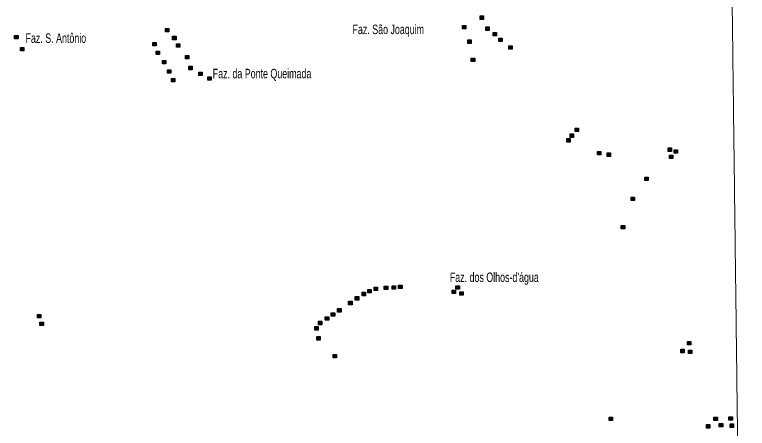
# Model space of a CAD drawing. Extents: x 265.7 to 292.1, y 7676.2 to 7704.2.
# Drawn here: x 285.92 to 292.1, y 7683.19 to 7686.68 of the extents above; entities that cross this region are included whole.
import ezdxf

# ---------------------------------------------------------------- set-up
doc = ezdxf.new("R2010")
doc.units = 0
doc.header["$LTSCALE"] = 0.032
doc.layers.add('2', color=7, linetype='Continuous', lineweight=25)
doc.layers.add('63', color=7, linetype='Continuous', lineweight=13)
doc.layers.add('61', color=7, linetype='Continuous')

msp = doc.modelspace()

# ---------------------------------------------------------------- hatches: boundary and pattern name
at = {"layer": '2'}
for points in [[(289.8456, 7686.6737), (289.8746, 7686.6737), (289.8746, 7686.6447), (289.8456, 7686.6447)], [(287.1895, 7686.5679), (287.2185, 7686.5679), (287.2185, 7686.5389), (287.1895, 7686.5389)], [(289.6962, 7686.5939), (289.7252, 7686.5939), (289.7252, 7686.5649), (289.6962, 7686.5649)], [(289.8931, 7686.5808), (289.9221, 7686.5808), (289.9221, 7686.5518), (289.8931, 7686.5518)], [(285.916, 7686.5098), (285.945, 7686.5098), (285.945, 7686.4808), (285.916, 7686.4808)], [(287.25, 7686.5019), (287.279, 7686.5019), (287.279, 7686.4729), (287.25, 7686.4729)], [(289.9561, 7686.5349), (289.9851, 7686.5349), (289.9851, 7686.5059), (289.9561, 7686.5059)], [(290.0045, 7686.4858), (290.0335, 7686.4858), (290.0335, 7686.4568), (290.0045, 7686.4568)], [(287.0822, 7686.4493), (287.1112, 7686.4493), (287.1112, 7686.4203), (287.0822, 7686.4203)], [(287.2823, 7686.4389), (287.3113, 7686.4389), (287.3113, 7686.4099), (287.2823, 7686.4099)], [(289.7422, 7686.4711), (289.7712, 7686.4711), (289.7712, 7686.4421), (289.7422, 7686.4421)], [(290.0875, 7686.4219), (290.1165, 7686.4219), (290.1165, 7686.3929), (290.0875, 7686.3929)], [(285.9644, 7686.4073), (285.9934, 7686.4073), (285.9934, 7686.3783), (285.9644, 7686.3783)], [(287.1104, 7686.3767), (287.1394, 7686.3767), (287.1394, 7686.3477), (287.1104, 7686.3477)], [(287.1638, 7686.2977), (287.1928, 7686.2977), (287.1928, 7686.2687), (287.1638, 7686.2687)], [(287.3575, 7686.3412), (287.3865, 7686.3412), (287.3865, 7686.3122), (287.3575, 7686.3122)], [(289.771, 7686.3172), (289.8, 7686.3172), (289.8, 7686.2882), (289.771, 7686.2882)], [(287.3864, 7686.2492), (287.4154, 7686.2492), (287.4154, 7686.2202), (287.3864, 7686.2202)], [(287.2056, 7686.22), (287.2346, 7686.22), (287.2346, 7686.191), (287.2056, 7686.191)], [(287.4712, 7686.2), (287.5002, 7686.2), (287.5002, 7686.171), (287.4712, 7686.171)], [(287.2396, 7686.1458), (287.2686, 7686.1458), (287.2686, 7686.1168), (287.2396, 7686.1168)], [(287.5463, 7686.1596), (287.5753, 7686.1596), (287.5753, 7686.1306), (287.5463, 7686.1306)], [(290.6065, 7685.6785), (290.6355, 7685.6785), (290.6355, 7685.6495), (290.6065, 7685.6495)], [(290.6478, 7685.7278), (290.6768, 7685.7278), (290.6768, 7685.6988), (290.6478, 7685.6988)], [(290.5776, 7685.639), (290.6066, 7685.639), (290.6066, 7685.61), (290.5776, 7685.61)], [(291.4336, 7685.5603), (291.4626, 7685.5603), (291.4626, 7685.5313), (291.4336, 7685.5313)], [(290.8365, 7685.5308), (290.8655, 7685.5308), (290.8655, 7685.5018), (290.8365, 7685.5018)], [(290.9189, 7685.518), (290.9479, 7685.518), (290.9479, 7685.489), (290.9189, 7685.489)], [(291.4451, 7685.4987), (291.4741, 7685.4987), (291.4741, 7685.4697), (291.4451, 7685.4697)], [(291.4838, 7685.5446), (291.5128, 7685.5446), (291.5128, 7685.5156), (291.4838, 7685.5156)], [(291.2361, 7685.3137), (291.2651, 7685.3137), (291.2651, 7685.2847), (291.2361, 7685.2847)], [(291.1208, 7685.146), (291.1498, 7685.146), (291.1498, 7685.117), (291.1208, 7685.117)], [(291.0376, 7684.9055), (291.0666, 7684.9055), (291.0666, 7684.8765), (291.0376, 7684.8765)], [(288.9513, 7684.3849), (288.9803, 7684.3849), (288.9803, 7684.3559), (288.9513, 7684.3559)], [(289.0369, 7684.3938), (289.0659, 7684.3938), (289.0659, 7684.3648), (289.0369, 7684.3648)], [(289.103, 7684.3961), (289.132, 7684.3961), (289.132, 7684.3671), (289.103, 7684.3671)], [(289.1579, 7684.4018), (289.1869, 7684.4018), (289.1869, 7684.3728), (289.1579, 7684.3728)], [(289.6421, 7684.397), (289.6711, 7684.397), (289.6711, 7684.368), (289.6421, 7684.368)], [(288.8495, 7684.3421), (288.8785, 7684.3421), (288.8785, 7684.3131), (288.8495, 7684.3131)], [(288.8973, 7684.3655), (288.9263, 7684.3655), (288.9263, 7684.3365), (288.8973, 7684.3365)], [(289.6092, 7684.3598), (289.6382, 7684.3598), (289.6382, 7684.3308), (289.6092, 7684.3308)], [(289.6736, 7684.3461), (289.7026, 7684.3461), (289.7026, 7684.3171), (289.6736, 7684.3171)], [(288.7359, 7684.2662), (288.7649, 7684.2662), (288.7649, 7684.2372), (288.7359, 7684.2372)], [(288.7923, 7684.3057), (288.8213, 7684.3057), (288.8213, 7684.2767), (288.7923, 7684.2767)], [(288.643, 7684.2041), (288.672, 7684.2041), (288.672, 7684.1751), (288.643, 7684.1751)], [(286.108, 7684.1557), (286.137, 7684.1557), (286.137, 7684.1267), (286.108, 7684.1267)], [(288.5389, 7684.1355), (288.5679, 7684.1355), (288.5679, 7684.1065), (288.5389, 7684.1065)], [(288.589, 7684.1695), (288.618, 7684.1695), (288.618, 7684.1405), (288.589, 7684.1405)], [(286.1298, 7684.0896), (286.1588, 7684.0896), (286.1588, 7684.0606), (286.1298, 7684.0606)], [(288.4808, 7684.0976), (288.5098, 7684.0976), (288.5098, 7684.0686), (288.4808, 7684.0686)], [(288.4501, 7684.0524), (288.4791, 7684.0524), (288.4791, 7684.0234), (288.4501, 7684.0234)], [(288.4671, 7683.9684), (288.4961, 7683.9684), (288.4961, 7683.9394), (288.4671, 7683.9394)], [(291.596, 7683.9265), (291.625, 7683.9265), (291.625, 7683.8975), (291.596, 7683.8975)], [(288.6042, 7683.8184), (288.6332, 7683.8184), (288.6332, 7683.7894), (288.6042, 7683.7894)], [(291.5402, 7683.8611), (291.5692, 7683.8611), (291.5692, 7683.8321), (291.5402, 7683.8321)], [(291.6057, 7683.8538), (291.6347, 7683.8538), (291.6347, 7683.8248), (291.6057, 7683.8248)], [(290.9358, 7683.289), (290.9648, 7683.289), (290.9648, 7683.26), (290.9358, 7683.26)], [(291.8204, 7683.2897), (291.8494, 7683.2897), (291.8494, 7683.2607), (291.8204, 7683.2607)], [(291.9473, 7683.2919), (291.9763, 7683.2919), (291.9763, 7683.2629), (291.9473, 7683.2629)], [(291.7567, 7683.2251), (291.7857, 7683.2251), (291.7857, 7683.1961), (291.7567, 7683.1961)], [(291.8649, 7683.2356), (291.8939, 7683.2356), (291.8939, 7683.2066), (291.8649, 7683.2066)], [(291.9576, 7683.2307), (291.9866, 7683.2307), (291.9866, 7683.2017), (291.9576, 7683.2017)]]:
    msp.add_hatch(color=256, dxfattribs=at).paths.add_polyline_path(points)

# ---------------------------------------------------------------- linework, layer by layer
for points in [[(289.8456, 7686.6737), (289.8746, 7686.6737), (289.8746, 7686.6447), (289.8456, 7686.6447)], [(287.1895, 7686.5679), (287.2185, 7686.5679), (287.2185, 7686.5389), (287.1895, 7686.5389)], [(289.6962, 7686.5939), (289.7252, 7686.5939), (289.7252, 7686.5649), (289.6962, 7686.5649)], [(289.8931, 7686.5808), (289.9221, 7686.5808), (289.9221, 7686.5518), (289.8931, 7686.5518)], [(285.916, 7686.5098), (285.945, 7686.5098), (285.945, 7686.4808), (285.916, 7686.4808)], [(287.25, 7686.5019), (287.279, 7686.5019), (287.279, 7686.4729), (287.25, 7686.4729)], [(289.9561, 7686.5349), (289.9851, 7686.5349), (289.9851, 7686.5059), (289.9561, 7686.5059)], [(290.0045, 7686.4858), (290.0335, 7686.4858), (290.0335, 7686.4568), (290.0045, 7686.4568)], [(287.0822, 7686.4493), (287.1112, 7686.4493), (287.1112, 7686.4203), (287.0822, 7686.4203)], [(287.2823, 7686.4389), (287.3113, 7686.4389), (287.3113, 7686.4099), (287.2823, 7686.4099)], [(289.7422, 7686.4711), (289.7712, 7686.4711), (289.7712, 7686.4421), (289.7422, 7686.4421)], [(290.0875, 7686.4219), (290.1165, 7686.4219), (290.1165, 7686.3929), (290.0875, 7686.3929)], [(285.9644, 7686.4073), (285.9934, 7686.4073), (285.9934, 7686.3783), (285.9644, 7686.3783)], [(287.1104, 7686.3767), (287.1394, 7686.3767), (287.1394, 7686.3477), (287.1104, 7686.3477)], [(287.1638, 7686.2977), (287.1928, 7686.2977), (287.1928, 7686.2687), (287.1638, 7686.2687)], [(287.3575, 7686.3412), (287.3865, 7686.3412), (287.3865, 7686.3122), (287.3575, 7686.3122)], [(289.771, 7686.3172), (289.8, 7686.3172), (289.8, 7686.2882), (289.771, 7686.2882)], [(287.3864, 7686.2492), (287.4154, 7686.2492), (287.4154, 7686.2202), (287.3864, 7686.2202)], [(287.2056, 7686.22), (287.2346, 7686.22), (287.2346, 7686.191), (287.2056, 7686.191)], [(287.4712, 7686.2), (287.5002, 7686.2), (287.5002, 7686.171), (287.4712, 7686.171)], [(287.2396, 7686.1458), (287.2686, 7686.1458), (287.2686, 7686.1168), (287.2396, 7686.1168)], [(287.5463, 7686.1596), (287.5753, 7686.1596), (287.5753, 7686.1306), (287.5463, 7686.1306)], [(290.6065, 7685.6785), (290.6355, 7685.6785), (290.6355, 7685.6495), (290.6065, 7685.6495)], [(290.6478, 7685.7278), (290.6768, 7685.7278), (290.6768, 7685.6988), (290.6478, 7685.6988)], [(290.5776, 7685.639), (290.6066, 7685.639), (290.6066, 7685.61), (290.5776, 7685.61)], [(291.4336, 7685.5603), (291.4626, 7685.5603), (291.4626, 7685.5313), (291.4336, 7685.5313)], [(290.8365, 7685.5308), (290.8655, 7685.5308), (290.8655, 7685.5018), (290.8365, 7685.5018)], [(290.9189, 7685.518), (290.9479, 7685.518), (290.9479, 7685.489), (290.9189, 7685.489)], [(291.4451, 7685.4987), (291.4741, 7685.4987), (291.4741, 7685.4697), (291.4451, 7685.4697)], [(291.4838, 7685.5446), (291.5128, 7685.5446), (291.5128, 7685.5156), (291.4838, 7685.5156)], [(291.2361, 7685.3137), (291.2651, 7685.3137), (291.2651, 7685.2847), (291.2361, 7685.2847)], [(291.1208, 7685.146), (291.1498, 7685.146), (291.1498, 7685.117), (291.1208, 7685.117)], [(291.0376, 7684.9055), (291.0666, 7684.9055), (291.0666, 7684.8765), (291.0376, 7684.8765)], [(288.9513, 7684.3849), (288.9803, 7684.3849), (288.9803, 7684.3559), (288.9513, 7684.3559)], [(289.0369, 7684.3938), (289.0659, 7684.3938), (289.0659, 7684.3648), (289.0369, 7684.3648)], [(289.103, 7684.3961), (289.132, 7684.3961), (289.132, 7684.3671), (289.103, 7684.3671)], [(289.1579, 7684.4018), (289.1869, 7684.4018), (289.1869, 7684.3728), (289.1579, 7684.3728)], [(289.6421, 7684.397), (289.6711, 7684.397), (289.6711, 7684.368), (289.6421, 7684.368)], [(288.8495, 7684.3421), (288.8785, 7684.3421), (288.8785, 7684.3131), (288.8495, 7684.3131)], [(288.8973, 7684.3655), (288.9263, 7684.3655), (288.9263, 7684.3365), (288.8973, 7684.3365)], [(289.6092, 7684.3598), (289.6382, 7684.3598), (289.6382, 7684.3308), (289.6092, 7684.3308)], [(289.6736, 7684.3461), (289.7026, 7684.3461), (289.7026, 7684.3171), (289.6736, 7684.3171)], [(288.7359, 7684.2662), (288.7649, 7684.2662), (288.7649, 7684.2372), (288.7359, 7684.2372)], [(288.7923, 7684.3057), (288.8213, 7684.3057), (288.8213, 7684.2767), (288.7923, 7684.2767)], [(288.643, 7684.2041), (288.672, 7684.2041), (288.672, 7684.1751), (288.643, 7684.1751)], [(286.108, 7684.1557), (286.137, 7684.1557), (286.137, 7684.1267), (286.108, 7684.1267)], [(288.5389, 7684.1355), (288.5679, 7684.1355), (288.5679, 7684.1065), (288.5389, 7684.1065)], [(288.589, 7684.1695), (288.618, 7684.1695), (288.618, 7684.1405), (288.589, 7684.1405)], [(286.1298, 7684.0896), (286.1588, 7684.0896), (286.1588, 7684.0606), (286.1298, 7684.0606)], [(288.4808, 7684.0976), (288.5098, 7684.0976), (288.5098, 7684.0686), (288.4808, 7684.0686)], [(288.4501, 7684.0524), (288.4791, 7684.0524), (288.4791, 7684.0234), (288.4501, 7684.0234)], [(288.4671, 7683.9684), (288.4961, 7683.9684), (288.4961, 7683.9394), (288.4671, 7683.9394)], [(291.596, 7683.9265), (291.625, 7683.9265), (291.625, 7683.8975), (291.596, 7683.8975)], [(288.6042, 7683.8184), (288.6332, 7683.8184), (288.6332, 7683.7894), (288.6042, 7683.7894)], [(291.5402, 7683.8611), (291.5692, 7683.8611), (291.5692, 7683.8321), (291.5402, 7683.8321)], [(291.6057, 7683.8538), (291.6347, 7683.8538), (291.6347, 7683.8248), (291.6057, 7683.8248)], [(290.9358, 7683.289), (290.9648, 7683.289), (290.9648, 7683.26), (290.9358, 7683.26)], [(291.8204, 7683.2897), (291.8494, 7683.2897), (291.8494, 7683.2607), (291.8204, 7683.2607)], [(291.9473, 7683.2919), (291.9763, 7683.2919), (291.9763, 7683.2629), (291.9473, 7683.2629)], [(291.7567, 7683.2251), (291.7857, 7683.2251), (291.7857, 7683.1961), (291.7567, 7683.1961)], [(291.8649, 7683.2356), (291.8939, 7683.2356), (291.8939, 7683.2066), (291.8649, 7683.2066)], [(291.9576, 7683.2307), (291.9866, 7683.2307), (291.9866, 7683.2017), (291.9576, 7683.2017)]]:
    msp.add_lwpolyline(points, close=True, dxfattribs=at)
at = {"layer": '63'}
msp.add_spline([(292.1022, 7676.5221), (292.0951, 7677.087), (292.088, 7677.6519), (292.081, 7678.2168), (292.0739, 7678.7818), (292.0668, 7679.3467), (292.0598, 7679.9116), (292.0527, 7680.4765), (292.0457, 7681.0414), (292.0386, 7681.6064), (292.0316, 7682.1713), (292.0245, 7682.7362), (292.0175, 7683.3011), (292.0104, 7683.866), (292.0034, 7684.431), (291.9963, 7684.9959), (291.9893, 7685.5608), (291.9822, 7686.1257), (291.9752, 7686.6906), (291.9681, 7687.2556), (291.9611, 7687.8205), (291.9541, 7688.3854), (291.947, 7688.9503), (291.94, 7689.5152), (291.933, 7690.0801), (291.9259, 7690.6451), (291.9189, 7691.21), (291.9119, 7691.7749), (291.9049, 7692.3398), (291.8978, 7692.9047), (291.8908, 7693.4696), (291.8838, 7694.0345), (291.8768, 7694.5995), (291.8698, 7695.1644), (291.8628, 7695.7293), (291.8557, 7696.2942), (291.8487, 7696.8591), (291.8417, 7697.424), (291.8347, 7697.9889), (291.8277, 7698.5539), (291.8207, 7699.1188), (291.8137, 7699.6837), (291.8067, 7700.2486), (291.7997, 7700.8135), (291.7927, 7701.3784), (291.7857, 7701.9433), (291.7787, 7702.5082), (291.7717, 7703.0731), (291.7647, 7703.638), (291.7577, 7704.203)], degree=3, dxfattribs=at)

# ---------------------------------------------------------------- texts
at = {"layer": '61', "width": 0.7}
for s, p in [('Faz. São Joaquim', (288.7688, 7686.5206)), ('Faz. S. Antônio', (286.0079, 7686.4468)), ('Faz. da Ponte Queimada', (287.5884, 7686.1476)), ("Faz. dos Olhos-d'água", (289.5902, 7684.429))]:
    msp.add_text(s, height=0.08, dxfattribs=at).set_placement(p)

doc.saveas('drawing.dxf')
